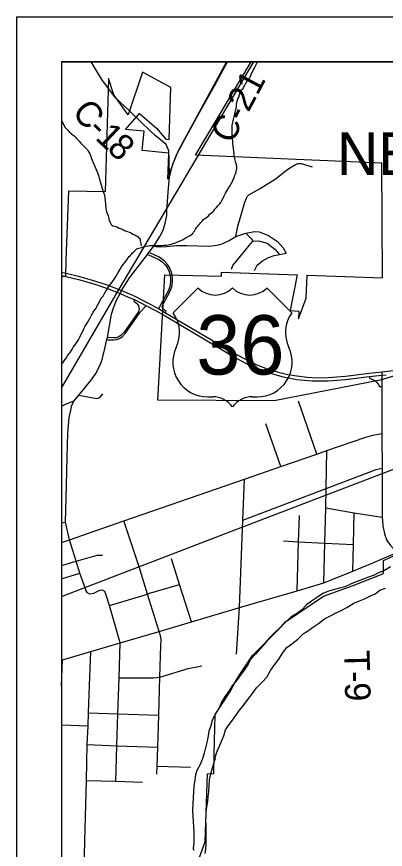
# Model space of a CAD drawing. Extents: x -14196 to 143, y -6096 to 28.
# Drawn here: x 58.003 to 58.823, y 21.949 to 23.799 of the extents above; entities that cross this region are included whole.
import ezdxf

# ---------------------------------------------------------------- set-up
doc = ezdxf.new("R2010")
doc.units = 0
for name, color, linetype in [('GM_X_City_Street', 7, 'Continuous'), ('GM_X_Corporation', 7, 'Continuous'), ('GM_X_Corporation_Text', 7, 'Continuous'), ('GM_X_County_Road', 7, 'Continuous'), ('GM_X_County_Road_Text', 7, 'Continuous'), ('GM_X_Interchange_Ramps', 7, 'Continuous'), ('GM_X_Major_River', 7, 'Continuous'), ('GM_X_Minor_River', 7, 'Continuous'), ('GM_X_Rail_Line', 7, 'Continuous'), ('GM_X_State_Route', 7, 'Continuous'), ('GM_X_Township_Road_Text', 7, 'Continuous'), ('GM_X_US_Location', 7, 'Continuous'), ('GM_X_US_Route', 7, 'Continuous'), ('GM_X_US_Shield', 7, 'Continuous'), ('SH_Data', 7, 'Continuous')]:
    doc.layers.add(name, color=color, linetype=linetype)

msp = doc.modelspace()

# ---------------------------------------------------------------- linework, layer by layer
at = {"layer": 'GM_X_City_Street'}
for p, q in [((58.6709, 22.8267), (58.6304, 22.9445)), ((58.5907, 22.7991), (58.5575, 22.8937)), ((58.1028, 22.6736), (58.1113, 22.6753)), ((58.1028, 22.5497), (58.1437, 22.5618)), ((58.2966, 22.5167), (58.365, 22.5373)), ((58.1642, 22.293), (58.1676, 22.388)), ((58.1028, 22.3112), (58.1048, 22.3697)), ((58.1028, 22.225), (58.1618, 22.2231)), ((58.3152, 22.133), (58.3898, 22.1311))]:
    msp.add_line(p, q, dxfattribs=at)
for points in [[(58.4906, 23.3103), (58.495, 23.3331), (58.5023, 23.3583), (58.5106, 23.3864), (58.5142, 23.3953), (58.5165, 23.3995), (58.5195, 23.4024), (58.543, 23.416), (58.5778, 23.4372), (58.6066, 23.4597), (58.6235, 23.4698), (58.6296, 23.472), (58.6363, 23.4724), (58.6608, 23.4652)], [(58.3079, 23.2883), (58.3166, 23.2872), (58.3364, 23.2881), (58.3584, 23.2902), (58.3816, 23.2902), (58.4311, 23.2889), (58.4485, 23.2905), (58.4604, 23.2941), (58.4759, 23.3011), (58.4906, 23.3103), (58.513, 23.3175), (58.5325, 23.3215), (58.5427, 23.3201), (58.5634, 23.3122), (58.5832, 23.2987), (58.5963, 23.2846), (58.6029, 23.2727)], [(58.513, 23.3175), (58.5248, 23.3058), (58.5286, 23.2994), (58.5408, 23.3006), (58.5606, 23.2955), (58.5771, 23.2823), (58.5876, 23.27)], [(58.4807, 23.2375), (58.4841, 23.246), (58.5117, 23.2791), (58.521, 23.291), (58.5286, 23.2994)], [(58.532, 23.2345), (58.5384, 23.2464), (58.5501, 23.256), (58.5634, 23.2633), (58.5763, 23.268), (58.5876, 23.27), (58.6029, 23.2727)], [(58.141, 22.9575), (58.1813, 22.9505), (58.1883, 22.9526), (58.1943, 22.9607)], [(58.1028, 22.9335), (58.1118, 22.9374), (58.1306, 22.9448)], [(58.6863, 22.5409), (58.6884, 22.6286), (58.6907, 22.7076), (58.6917, 22.7503), (58.693, 22.8344)], [(58.5059, 22.6799), (58.6917, 22.7503), (58.8028, 22.7922), (58.816, 22.7957)], [(58.4923, 22.3823), (58.4987, 22.4855), (58.5059, 22.6799), (58.5099, 22.7712)], [(58.6907, 22.7076), (58.7543, 22.6964), (58.8166, 22.6862)], [(58.627, 22.5229), (58.6304, 22.6321), (58.6324, 22.6906)], [(58.7509, 22.5663), (58.7522, 22.6261), (58.7543, 22.6964)], [(58.3149, 22.1159), (58.3152, 22.133), (58.317, 22.1757), (58.3191, 22.247), (58.3214, 22.3313), (58.3239, 22.4025), (58.3242, 22.4124), (58.3236, 22.4203), (58.3203, 22.4328), (58.2937, 22.5158), (58.2756, 22.576), (58.2412, 22.6784)], [(58.1571, 22.524), (58.1565, 22.5249), (58.1437, 22.5618), (58.1356, 22.5887), (58.1205, 22.6363)], [(58.5965, 22.6343), (58.6304, 22.6321), (58.6884, 22.6286), (58.7522, 22.6261)], [(58.1028, 22.5793), (58.1356, 22.5887), (58.1819, 22.6024), (58.1939, 22.6024)], [(58.3917, 22.4541), (58.365, 22.5373), (58.3476, 22.5936)], [(58.2333, 22.4072), (58.2092, 22.4904), (58.2022, 22.5132), (58.1991, 22.5213), (58.1939, 22.5244), (58.1874, 22.5236), (58.1739, 22.5169), (58.1659, 22.5153), (58.1607, 22.5187), (58.1571, 22.524)], [(58.2092, 22.4904), (58.2937, 22.5158), (58.2966, 22.5167)], [(58.2237, 22.1), (58.2257, 22.1787), (58.228, 22.2494), (58.2308, 22.3298), (58.2333, 22.4072)], [(58.2308, 22.3298), (58.3084, 22.3293), (58.3214, 22.3313), (58.3846, 22.35), (58.4149, 22.356)], [(58.1532, 21.903), (58.1543, 21.9668), (58.1586, 22.1016), (58.1596, 22.1811), (58.1618, 22.2231), (58.1627, 22.2518), (58.1642, 22.293)], [(58.1627, 22.2518), (58.228, 22.2494), (58.3191, 22.247)], [(58.1596, 22.1811), (58.2257, 22.1787), (58.317, 22.1757)], [(58.1586, 22.1016), (58.2237, 22.1), (58.2833, 22.098)]]:
    msp.add_lwpolyline(points, dxfattribs=at)
at = {"layer": 'GM_X_Corporation'}
for points in [[(64.9028, 18.7286), (64.9028, 23.6985), (58.1028, 23.6985), (58.1028, 18.8711)], [(58.9467, 23.0311), (58.8117, 22.9912), (58.5758, 22.9449), (58.3174, 22.9468), (58.3329, 23.2251), (58.459, 23.2221), (58.4591, 23.2311), (58.627, 23.2251), (58.6112, 23.1454), (58.6309, 23.1444), (58.6299, 23.1275), (58.6468, 23.1729), (58.6496, 23.2243), (58.8173, 23.2184), (58.8153, 23.4727), (58.4006, 23.4908), (58.5246, 23.6985), (58.4702, 23.6985), (58.3623, 23.5007), (58.3501, 23.4717), (58.3396, 23.4374), (58.3414, 23.4951), (58.2823, 23.5012), (58.2867, 23.5439), (58.2451, 23.5481), (58.2759, 23.5837), (58.3144, 23.5506), (58.3352, 23.526), (58.3423, 23.5254), (58.3458, 23.6411), (58.2826, 23.6754), (58.2508, 23.5806), (58.219, 23.6251), (58.2071, 23.6614), (58.2001, 23.4092), (58.118, 23.4108), (58.1122, 23.258), (58.1118, 23.2217), (58.1028, 23.2195), (58.1028, 21.5984)], [(62.1999, 18.7816), (62.2235, 19.866), (62.2323, 20.4208), (62.2487, 21.1358), (62.2751, 22.2884), (62.2815, 22.5484), (62.2824, 22.5866), (62.306, 23.4402), (61.9207, 23.4521), (60.7524, 23.485), (60.7179, 23.4857), (60.6994, 23.486), (60.6731, 23.4865), (60.4232, 23.4912), (60.4233, 23.5426), (60.4242, 23.5839), (60.4246, 23.6029), (60.4257, 23.6513), (60.4267, 23.6985), (58.1028, 23.6985), (58.1028, 18.8711)], [(58.3377, 21.7363), (58.4221, 21.9651), (58.4273, 22.1163), (58.4418, 22.1169), (58.4426, 22.1596), (58.4444, 22.2484), (58.4775, 22.2974), (58.4901, 22.3215), (58.4983, 22.3346), (58.5276, 22.3789), (58.5518, 22.4026), (58.562, 22.4137), (58.5625, 22.4142), (58.582, 22.4329), (58.5918, 22.443), (58.6012, 22.4541), (58.6859, 22.511), (58.7518, 22.535), (58.8178, 22.5607), (58.8196, 22.5625), (58.8195, 22.5901), (58.8505, 22.6042)]]:
    msp.add_lwpolyline(points, dxfattribs=at)
at = {"layer": 'GM_X_County_Road'}
for p, q in [((58.1028, 22.6305), (58.1205, 22.6363)), ((58.8216, 22.5961), (58.8496, 22.6079)), ((58.7937, 22.5843), (58.8216, 22.5961))]:
    msp.add_line(p, q, dxfattribs=at)
for points in [[(58.3433, 23.442), (58.342, 23.4828), (58.3417, 23.5007), (58.3353, 23.5147), (58.3111, 23.5346), (58.2838, 23.5601), (58.2537, 23.5893), (58.2225, 23.6181), (58.1923, 23.6588), (58.1733, 23.6904), (58.1689, 23.6985)], [(58.3433, 23.442), (58.3504, 23.4706), (58.3594, 23.493), (58.3814, 23.5342), (58.4097, 23.5853), (58.4429, 23.6452), (58.4724, 23.6985)], [(58.1914, 23.0326), (58.1936, 23.0401), (58.1991, 23.0613), (58.2034, 23.0813), (58.2049, 23.0858), (58.2141, 23.1372), (58.2182, 23.1517), (58.2249, 23.1687), (58.2329, 23.1835), (58.236, 23.1901), (58.2541, 23.2183), (58.2938, 23.2701), (58.297, 23.2742), (58.3079, 23.2883), (58.3213, 23.3099), (58.3286, 23.324), (58.3334, 23.3397), (58.337, 23.3567), (58.3372, 23.3662), (58.3397, 23.4086), (58.3433, 23.442)], [(58.1205, 22.6363), (58.1113, 22.6753), (58.114, 22.7578), (58.1154, 22.8195), (58.1165, 22.8731), (58.12, 22.908), (58.1233, 22.9243), (58.126, 22.935), (58.1306, 22.9448), (58.141, 22.9575), (58.1553, 22.9743), (58.1709, 22.994), (58.1805, 23.0083), (58.1858, 23.0187), (58.1904, 23.0289), (58.1914, 23.0326)], [(58.1205, 22.6363), (58.2412, 22.6784), (58.5099, 22.7712), (58.5907, 22.7991), (58.6709, 22.8267), (58.693, 22.8344), (58.7797, 22.8642), (58.7952, 22.8686), (58.8153, 22.8723)], [(58.4968, 22.4849), (58.4987, 22.4855), (58.627, 22.5229), (58.6863, 22.5409), (58.7509, 22.5663), (58.7937, 22.5843)], [(58.1028, 22.3691), (58.1048, 22.3697), (58.1676, 22.388), (58.2333, 22.4072), (58.3203, 22.4328), (58.3917, 22.4541), (58.4968, 22.4849)]]:
    msp.add_lwpolyline(points, dxfattribs=at)
at = {"layer": 'GM_X_Interchange_Ramps'}
for points in [[(58.3499, 23.2157), (58.3499, 23.2168), (58.3489, 23.2246), (58.3469, 23.2323), (58.3428, 23.2411), (58.3385, 23.2476), (58.3321, 23.2551), (58.3247, 23.2614), (58.3186, 23.2648), (58.3005, 23.2727), (58.297, 23.2742)], [(58.2938, 23.2701), (58.2977, 23.2684), (58.3165, 23.2604), (58.3207, 23.2583), (58.3276, 23.2529), (58.3331, 23.2469), (58.3382, 23.2396), (58.3423, 23.2315), (58.3445, 23.2237), (58.3453, 23.2162), (58.3456, 23.2094), (58.344, 23.1992), (58.3408, 23.1903), (58.3207, 23.1542), (58.3186, 23.1505)], [(58.3279, 23.1579), (58.3287, 23.1597), (58.3446, 23.1884), (58.3483, 23.1984), (58.3499, 23.2083), (58.3499, 23.2157)], [(58.265, 23.1698), (58.2636, 23.1665), (58.2697, 23.1619), (58.2738, 23.1558), (58.2751, 23.1523), (58.2756, 23.1486), (58.275, 23.1447), (58.2735, 23.1418), (58.2418, 23.0976), (58.2356, 23.0912), (58.2302, 23.0875), (58.2242, 23.0852), (58.219, 23.0847), (58.2068, 23.0854), (58.2049, 23.0858)], [(58.2034, 23.0813), (58.2066, 23.0808), (58.2191, 23.0805), (58.2251, 23.0813), (58.2314, 23.0837), (58.2384, 23.0882), (58.2449, 23.0956), (58.2774, 23.1418), (58.2894, 23.1548), (58.2907, 23.157)], [(58.3342, 23.1407), (58.3356, 23.1433), (58.3317, 23.1467), (58.3282, 23.1498), (58.3271, 23.1516), (58.3266, 23.1531), (58.3266, 23.1546), (58.3271, 23.156), (58.3279, 23.1579)], [(58.7875, 22.9988), (58.7879, 22.995), (58.7934, 22.9934), (58.7997, 22.99), (58.802, 22.9881)], [(58.802, 22.9881), (58.8036, 22.9868), (58.8073, 22.9821), (58.8101, 22.977), (58.8154, 22.9769)]]:
    msp.add_lwpolyline(points, dxfattribs=at)
at = {"layer": 'GM_X_Major_River'}
for points in [[(58.8346, 22.5763), (58.8218, 22.5681), (58.8097, 22.5638), (58.7984, 22.558), (58.7859, 22.5529), (58.7727, 22.5478), (58.7587, 22.5427), (58.7455, 22.5376), (58.7331, 22.5321), (58.7213, 22.5289), (58.71, 22.5257), (58.6971, 22.5218), (58.6843, 22.5167), (58.6723, 22.5089), (58.6591, 22.5001), (58.6478, 22.4916), (58.6373, 22.4808), (58.6257, 22.4719), (58.6133, 22.4642), (58.6005, 22.4526), (58.5889, 22.4403), (58.5765, 22.4292), (58.5645, 22.4176), (58.5548, 22.4061), (58.5447, 22.3942), (58.5346, 22.382), (58.5234, 22.3701), (58.5182, 22.3601), (58.5093, 22.3467), (58.5003, 22.3349), (58.4936, 22.3253), (58.4831, 22.3134), (58.4768, 22.3023), (58.4671, 22.2885), (58.459, 22.2755), (58.4534, 22.2629), (58.4445, 22.2492), (58.4382, 22.235), (58.4339, 22.2209), (58.4309, 22.2114), (58.4288, 22.2008), (58.4267, 22.1886), (58.4234, 22.1741), (58.4198, 22.1623), (58.4162, 22.1498), (58.4103, 22.1356), (58.404, 22.1234), (58.4011, 22.1139), (58.3993, 22.1032), (58.3968, 22.0888), (58.3962, 22.077), (58.3956, 22.0633), (58.3947, 22.0504), (58.3941, 22.0352), (58.3947, 22.022), (58.3959, 22.0098), (58.3965, 21.9992), (58.397, 21.9867), (58.3973, 21.9632), (58.3959, 21.9506), (58.3971, 21.9465)], [(58.4457, 22.152), (58.445, 22.1535), (58.449, 22.1665), (58.4534, 22.176), (58.4589, 22.1886), (58.4641, 22.2008), (58.4677, 22.2138), (58.4737, 22.2233), (58.4834, 22.2352), (58.4905, 22.2456), (58.499, 22.2578), (58.5072, 22.2674), (58.5177, 22.2812), (58.5274, 22.2946), (58.5363, 22.3076), (58.5491, 22.3199), (58.5599, 22.3314), (58.5681, 22.3456), (58.5767, 22.3586), (58.5864, 22.3712), (58.5945, 22.3843), (58.6043, 22.3969), (58.6151, 22.4054), (58.6283, 22.4158), (58.6403, 22.427), (58.6501, 22.4331), (58.6614, 22.4413), (58.6749, 22.4502), (58.6877, 22.4606), (58.6997, 22.4668), (58.7126, 22.473), (58.7254, 22.4793), (58.7378, 22.4859), (58.7529, 22.4952), (58.7657, 22.501), (58.777, 22.5053), (58.7902, 22.5119), (58.8004, 22.5163), (58.811, 22.524), (58.8238, 22.5287)], [(58.4227, 21.9396), (58.4237, 21.9491), (58.4243, 21.9597), (58.4249, 21.9692), (58.4245, 22.0026), (58.424, 22.0125), (58.4243, 22.022), (58.4249, 22.0322), (58.4263, 22.0425), (58.4284, 22.0554), (58.4294, 22.0649), (58.4304, 22.0774), (58.431, 22.09), (58.4323, 22.1033), (58.4352, 22.1162), (58.4388, 22.1295), (58.4417, 22.1391), (58.4457, 22.152)]]:
    msp.add_lwpolyline(points, dxfattribs=at)
at = {"layer": 'GM_X_Minor_River'}
for points in [[(58.487, 23.4933), (58.4862, 23.4998), (58.4854, 23.5055), (58.4846, 23.5111), (58.4842, 23.5172), (58.4838, 23.5218), (58.4834, 23.5271), (58.483, 23.532), (58.4826, 23.5366), (58.4822, 23.5411), (58.4822, 23.5461), (58.4822, 23.551), (58.4822, 23.5548), (58.4826, 23.5579), (58.4829, 23.5601), (58.4837, 23.5632), (58.4844, 23.5677), (58.4852, 23.5704), (58.4859, 23.5731), (58.4867, 23.5761), (58.4874, 23.5795), (58.4882, 23.5826), (58.4893, 23.5856), (58.49, 23.5902), (58.4912, 23.5936), (58.4919, 23.5989), (58.4923, 23.6042), (58.4938, 23.6107), (58.4953, 23.616), (58.4975, 23.6198), (58.5002, 23.6297), (58.504, 23.6365), (58.5066, 23.6392), (58.5077, 23.6415), (58.5096, 23.6449), (58.5123, 23.6495), (58.5153, 23.6544), (58.5191, 23.6601), (58.5225, 23.664), (58.5251, 23.67), (58.5285, 23.6784), (58.5327, 23.686), (58.5365, 23.694), (58.5387, 23.6985)], [(58.1028, 23.5686), (58.103, 23.5683), (58.1057, 23.563), (58.108, 23.5577), (58.111, 23.5524), (58.1145, 23.5486), (58.1172, 23.5459), (58.1198, 23.5429), (58.1233, 23.5399), (58.1259, 23.5376), (58.1279, 23.5361), (58.1305, 23.5334), (58.1336, 23.5308), (58.1363, 23.5278), (58.1393, 23.5251), (58.142, 23.5217), (58.145, 23.5183), (58.1481, 23.5149), (58.1515, 23.5115), (58.1546, 23.5085), (58.1577, 23.5054), (58.1603, 23.5028), (58.1622, 23.4997), (58.1649, 23.4952), (58.1672, 23.4903), (58.1695, 23.4834), (58.1726, 23.4759), (58.1753, 23.4694), (58.1776, 23.4645), (58.1838, 23.4501), (58.1853, 23.4459), (58.1868, 23.4398), (58.1884, 23.4322), (58.1911, 23.425), (58.1934, 23.4171), (58.1957, 23.4102), (58.1972, 23.4061), (58.198, 23.4019), (58.1992, 23.3958), (58.2, 23.389), (58.2008, 23.3818), (58.2012, 23.3738), (58.2023, 23.3677), (58.2039, 23.3632), (58.2054, 23.3594), (58.2062, 23.3563), (58.207, 23.3529), (58.2077, 23.3503), (58.2085, 23.3465), (58.21, 23.3427), (58.212, 23.34), (58.2131, 23.337), (58.2146, 23.3351), (58.2166, 23.334), (58.2207, 23.3328), (58.2234, 23.3321), (58.2257, 23.3317), (58.2276, 23.3306), (58.2307, 23.3287), (58.2341, 23.3276), (58.236, 23.3268), (58.239, 23.3257), (58.2432, 23.3234), (58.2497, 23.3212), (58.2532, 23.3197), (58.2554, 23.3189), (58.2581, 23.3174), (58.2612, 23.3155), (58.2631, 23.3148), (58.2657, 23.314), (58.268, 23.3125), (58.2707, 23.3106), (58.273, 23.3091), (58.2757, 23.3061), (58.2776, 23.3046), (58.278, 23.3004), (58.2791, 23.2943), (58.2799, 23.2894), (58.2803, 23.289)], [(58.2287, 23.2303), (58.2329, 23.2372), (58.2363, 23.2429), (58.2401, 23.2478), (58.2435, 23.2524), (58.2465, 23.2562), (58.2488, 23.2593), (58.2511, 23.2627), (58.2534, 23.2654), (58.2553, 23.2673), (58.2571, 23.2695), (58.259, 23.2718), (58.2609, 23.2737), (58.2632, 23.2756), (58.2651, 23.2772), (58.267, 23.2798), (58.27, 23.2825), (58.2719, 23.2833), (58.275, 23.2844), (58.2776, 23.2852), (58.2807, 23.286), (58.2841, 23.2871), (58.2879, 23.2879), (58.2917, 23.2887), (58.2955, 23.2894), (58.2993, 23.2898), (58.3031, 23.2898), (58.318, 23.2899), (58.3225, 23.2899), (58.3267, 23.2903), (58.3313, 23.2907), (58.3359, 23.2911), (58.34, 23.2919), (58.3435, 23.2923), (58.3473, 23.293), (58.3507, 23.2942), (58.3541, 23.2953), (58.3575, 23.2969), (58.361, 23.2984), (58.3655, 23.2999), (58.3682, 23.3011), (58.3716, 23.3026), (58.3754, 23.3049), (58.38, 23.3076), (58.3849, 23.3099), (58.3891, 23.3122), (58.3921, 23.3145), (58.3948, 23.3168), (58.3967, 23.3194), (58.3986, 23.3221), (58.4008, 23.3266), (58.4035, 23.3305), (58.4057, 23.3331), (58.408, 23.3358), (58.4103, 23.3385), (58.4126, 23.3411), (58.416, 23.3442), (58.419, 23.3476), (58.4228, 23.3507), (58.4262, 23.3533), (58.4296, 23.356), (58.4331, 23.3594), (58.4365, 23.3625), (58.4391, 23.3648), (58.4414, 23.3674), (58.4441, 23.3709), (58.4475, 23.3747), (58.4509, 23.3785), (58.4543, 23.3819), (58.4569, 23.3857), (58.4596, 23.3903), (58.4622, 23.3952), (58.4649, 23.4002), (58.4679, 23.4066), (58.4702, 23.4104), (58.4721, 23.4139), (58.4736, 23.4165), (58.4785, 23.4245), (58.4804, 23.4272), (58.4819, 23.4295), (58.483, 23.4329), (58.4849, 23.4371), (58.4868, 23.4405), (58.4879, 23.4432), (58.4887, 23.4466), (58.4902, 23.4496), (58.4909, 23.4519), (58.4913, 23.4538), (58.4921, 23.4565), (58.4924, 23.4591), (58.4932, 23.461), (58.4932, 23.4629), (58.4928, 23.4656), (58.4924, 23.4675), (58.492, 23.4698), (58.4913, 23.4721), (58.4905, 23.4739), (58.4897, 23.4762), (58.4889, 23.4804), (58.4878, 23.4865), (58.487, 23.4933)], [(58.1028, 23.0254), (58.1043, 23.0278), (58.1073, 23.032), (58.11, 23.0358), (58.113, 23.04), (58.116, 23.045), (58.119, 23.0495), (58.1217, 23.0526), (58.124, 23.056), (58.1262, 23.0594), (58.1285, 23.064), (58.1319, 23.0678), (58.1349, 23.072), (58.1376, 23.0762), (58.1402, 23.0808), (58.1429, 23.0853), (58.1459, 23.0914), (58.1493, 23.0986), (58.1527, 23.1051), (58.1557, 23.1108), (58.1584, 23.1154), (58.1607, 23.1192), (58.1637, 23.1245), (58.1663, 23.1295), (58.1693, 23.1356), (58.1731, 23.142), (58.1769, 23.1474), (58.1796, 23.1508), (58.1811, 23.1538), (58.183, 23.1573), (58.1849, 23.1607), (58.1913, 23.1732), (58.1951, 23.1778), (58.1985, 23.1831), (58.2015, 23.1888), (58.2049, 23.1945), (58.2091, 23.2006), (58.2132, 23.206), (58.2166, 23.2105), (58.2197, 23.2151), (58.2227, 23.2201), (58.2257, 23.225), (58.2287, 23.2303)]]:
    msp.add_lwpolyline(points, dxfattribs=at)
at = {"layer": 'GM_X_Rail_Line'}
for points in [[(58.1028, 22.5102), (58.5061, 22.6648), (59.0457, 22.8709), (59.6972, 23.1194), (60.0189, 23.2424), (60.3358, 23.3635), (60.5045, 23.428), (60.5632, 23.4504), (60.5938, 23.4628), (60.6201, 23.474), (60.6495, 23.4872), (60.6788, 23.5017), (60.7158, 23.5204), (60.7465, 23.5379), (60.7724, 23.5535), (60.7959, 23.5682), (60.8339, 23.5931), (60.8671, 23.6168), (60.8984, 23.6407), (60.9307, 23.6668), (60.9677, 23.6985)], [(58.1028, 22.9735), (58.2285, 23.1891), (58.5309, 23.6985)]]:
    msp.add_lwpolyline(points, dxfattribs=at)
at = {"layer": 'GM_X_State_Route'}
for points in [[(58.8154, 23.0095), (58.8155, 23.002), (58.8154, 22.9769), (58.8153, 22.8723), (58.8154, 22.862), (58.816, 22.8008)], [(58.816, 22.8008), (58.816, 22.7957), (58.8163, 22.74)], [(58.8163, 22.74), (58.8166, 22.6862), (58.8176, 22.6692), (58.8178, 22.6662), (58.8212, 22.6503), (58.8215, 22.6493)], [(58.8215, 22.6493), (58.8268, 22.6346), (58.8346, 22.6233), (58.8424, 22.6152)]]:
    msp.add_lwpolyline(points, dxfattribs=at)
at = {"layer": 'GM_X_US_Route'}
msp.add_line((58.3186, 23.1505), (58.3342, 23.1407), dxfattribs=at)
for points in [[(58.1028, 23.2306), (58.1157, 23.228), (58.1404, 23.2218), (58.1712, 23.2131), (58.2021, 23.2032), (58.236, 23.1901), (58.2537, 23.1829), (58.2671, 23.177), (58.2943, 23.163), (58.3186, 23.1505)], [(58.1028, 23.2232), (58.1082, 23.2223), (58.1122, 23.2213)], [(58.1122, 23.2213), (58.1406, 23.2144), (58.1747, 23.2048), (58.2054, 23.1945), (58.2329, 23.1835), (58.2493, 23.1763), (58.265, 23.1698), (58.2907, 23.157), (58.315, 23.1444), (58.3307, 23.1353), (58.3332, 23.1338)], [(58.3332, 23.1338), (58.4927, 23.0391), (58.5154, 23.0273), (58.5398, 23.016), (58.5668, 23.0064), (58.5963, 22.9984), (58.6267, 22.9927), (58.6608, 22.9893)], [(58.3342, 23.1407), (58.492, 23.0481), (58.5135, 23.0366), (58.5374, 23.0252), (58.5606, 23.016), (58.5827, 23.0092), (58.6063, 23.0032), (58.6266, 23.0002), (58.6491, 22.9975), (58.6724, 22.996), (58.696, 22.9966), (58.7347, 22.9996), (58.7875, 23.0063), (58.8154, 23.0095), (59.201, 23.0541), (59.305, 23.067), (59.3404, 23.0726)], [(58.6608, 22.9893), (58.696, 22.9891), (58.7347, 22.9921), (58.7875, 22.9988), (58.8155, 23.002), (58.8254, 23.0031)]]:
    msp.add_lwpolyline(points, dxfattribs=at)
at = {"layer": 'GM_X_US_Shield'}
for p, q in [((58.4063, 23.1956), (58.3513, 23.1407)), ((58.615, 23.1407), (58.5601, 23.1956)), ((58.4282, 22.9539), (58.4392, 22.9539)), ((58.5271, 22.9539), (58.5381, 22.9539))]:
    msp.add_line(p, q, dxfattribs=at)
for centre, radius, start, end in [((58.4447, 23.2349), 0.0549, 225.573, 314.427), ((58.5216, 23.2349), 0.0549, 225.573, 314.427), ((58.2883, 23.0966), 0.0769, 334.5471, 35.0009), ((58.678, 23.0966), 0.0769, 144.9991, 205.4529), ((58.4274, 23.0308), 0.0769, 154.8319, 270.6383), ((58.539, 23.0308), 0.0769, 269.3617, 25.1681), ((58.4392, 22.899), 0.0549, 36.8699, 90), ((58.5271, 22.899), 0.0549, 90, 143.1301)]:
    msp.add_arc(centre, radius, start, end, dxfattribs=at)
at = {"layer": 'SH_Data'}
for p, q in [((58.0028, 23.7985), (65.0028, 23.7985)), ((58.0028, 23.7985), (58.0028, 16.7985)), ((58.1028, 23.6985), (58.1028, 16.8985)), ((58.1028, 23.6985), (64.9028, 23.6985))]:
    msp.add_line(p, q, dxfattribs=at)

# ---------------------------------------------------------------- texts
at = {"layer": 'GM_X_Corporation_Text'}
msp.add_text('NEWCOMERSTOWN', height=0.094697, rotation=0, dxfattribs=at).set_placement((58.7161, 23.4468))
at = {"layer": 'GM_X_County_Road_Text'}
for s, height, rotation, p in [('C-21', 0.05682, 62.0503, (58.4813, 23.5135)), ('C', 0.0568, 309.2474, (58.1241, 23.5858)), ('-', 0.0568, 315.3258, (58.1581, 23.5448)), ('1', 0.0568, 316.6332, (58.1757, 23.5274)), ('8', 0.0568, 317.2645, (58.2016, 23.5029))]:
    msp.add_text(s, height=height, rotation=rotation, dxfattribs=at).set_placement(p)
at = {"layer": 'GM_X_Township_Road_Text'}
msp.add_text('T-9', height=0.05682, rotation=271.4332, dxfattribs=at).set_placement((58.7313, 22.3905))
at = {"layer": 'GM_X_US_Location'}
for s in ['0', '/']:
    msp.add_text(s, height=0.000189, dxfattribs=at).set_placement((58.4831, 23.0682))
msp.add_text('36', height=0.000189, rotation=0, dxfattribs=at).set_placement((58.444, 23.029))
at = {"layer": 'GM_X_US_Shield'}
msp.add_text('36', height=0.13184, dxfattribs=at).set_placement((58.4028, 23.0034))

doc.saveas('drawing.dxf')
